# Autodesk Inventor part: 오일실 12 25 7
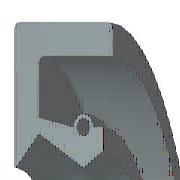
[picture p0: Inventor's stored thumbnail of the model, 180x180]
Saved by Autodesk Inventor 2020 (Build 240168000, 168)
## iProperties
Created: 2012-02
Part Number: 오일실 12 25 7
Material: 고무
Description: 오일-실
Document SubType Name: Modeling
Standard: KS B 2804
Designer: test
Standards Organization: KS
Language: ko-KR
Size Designation: D - 12 25 7
Categories: <MemberInstance><Categories><Category DisplayName="샤프트 부품" InternalName="7f7aeb1f-a693-4053-b835-cee3144e0d98" Mnemonic="SHFT"><Category DisplayName="실링" Intern
Density: 0.93 g/cm^3
Appearance: 고무 - 검은색 - 버전 1.1
IsCustomPart: 1
Author: test
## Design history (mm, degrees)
revolve "본체" stored, may be unused: angle "d17" = 90 deg
revolve "스프링1" stored, may be unused: angle "d18" = 90 deg
body "Solid1"
sketch "스케치1"
  geometry: L1 (0, 12.5)-(7, 12.5); L2 (7, 10.75)-(1.75, 10.75); L3 (1.75, 7.75)-(4.9, 6); L4 (4.9, 6)-(0, 6); L5 (0, 0)-(9.586, 0) reference; L6 (4.9, 6)-(6.3, 6.875); L7 (0, 18)-(0, -3) reference; L8 (-1.941, 0)-(11.507, 0) reference; L9 (4.2, 8.1)-(1.75, 8.59); L10 (1.75, 8.59)-(1.75, 10.75); L11 (0, 12.5)-(0, 6.088); L12 (4.9, 6)-(0, 6); L13 (1.75, 7.75)-(0.152, 6.028); L14 (7, 12.5)-(7, 10.75); L15 (5.6, 8.1)-(6.3, 8.1); L16 (6.3, 8.1)-(6.3, 6.875); C1 r 0.455 at (4.9, 8.1); A1 r 0.7 centre (4.9, 8.1) between (5.6, 8.1) and (4.2, 8.1); A2 r 0.088 centre (0.088, 6.088) between (0, 6.088) and (0.152, 6.028); 1 further point
  constraints: 28 end point, 5 horizontal alignment, 5 point on line, 4 point on circle, 4 vertical alignment, 3 centre point, 3 tangent, 2 collinear, 2 horizontal, 2 perpendicular, 1 coincident, 1 parallel
  dimensions: "d0" = 25 diameter of L1 L5 (= SD2); "d1" = 1.75 distance of L1.end L2.start (= SD); "d2" = 0.91 diameter of C1 (= SPDI); "d3" = 1.4 diameter of A1 (= SPDA); "d4" = 12 diameter of L3.end L5 (= NND); "d5" = 15.5 diameter of L3.start L5 (= TKDM); "d7" = 17.18 diameter of L9.end L5 (= TKDM + 0.24 x SWDT); "d8" = 1.75 distance between parallel lines of L11 L10 (= SD); "d9" = 4.9 distance from line of L11 C1.centre (= SPDST); "d10" = 16.2 diameter of C1.centre L5 (= HLDM); "d11" = 0.0875 radius of A2 (= 0.25 x LAB); "d12" = 6.3 distance between parallel lines of L11 L16 (= SDI); "d13" = 13.75 diameter of L6.end L5 (= ABDM); "d14" = 7 distance from line of L11 L1.end (= SWDT)
fillet "모깎기1" dims "d6" = 0.3 (= RR)
other parameters: "SD2" = 25 [user parameter; used in 1 equation term], "SWDT" = 7 [user parameter; used in 2 equation terms], "RR" = 0.3 [user parameter; used in 1 equation term], "SD" = 1.75 [user parameter; used in 2 equation terms], "NND" = 12 [user parameter; used in 1 equation term], "SPDA" = 1.4 [user parameter; used in 1 equation term], "SPDI" = 0.91 [user parameter; used in 1 equation term], "TKDM" = 15.5 [user parameter; used in 2 equation terms], "HLDM" = 16.2 [user parameter; used in 1 equation term], "ABDM" = 13.75 [user parameter; used in 1 equation term], "SDI" = 6.3 [user parameter; used in 1 equation term], "SPDST" = 4.9 [user parameter; used in 1 equation term], "LAB" = 0.35 [user parameter; used in 1 equation term], "d15" = 0, "d16" = 0, "d19" = 0
